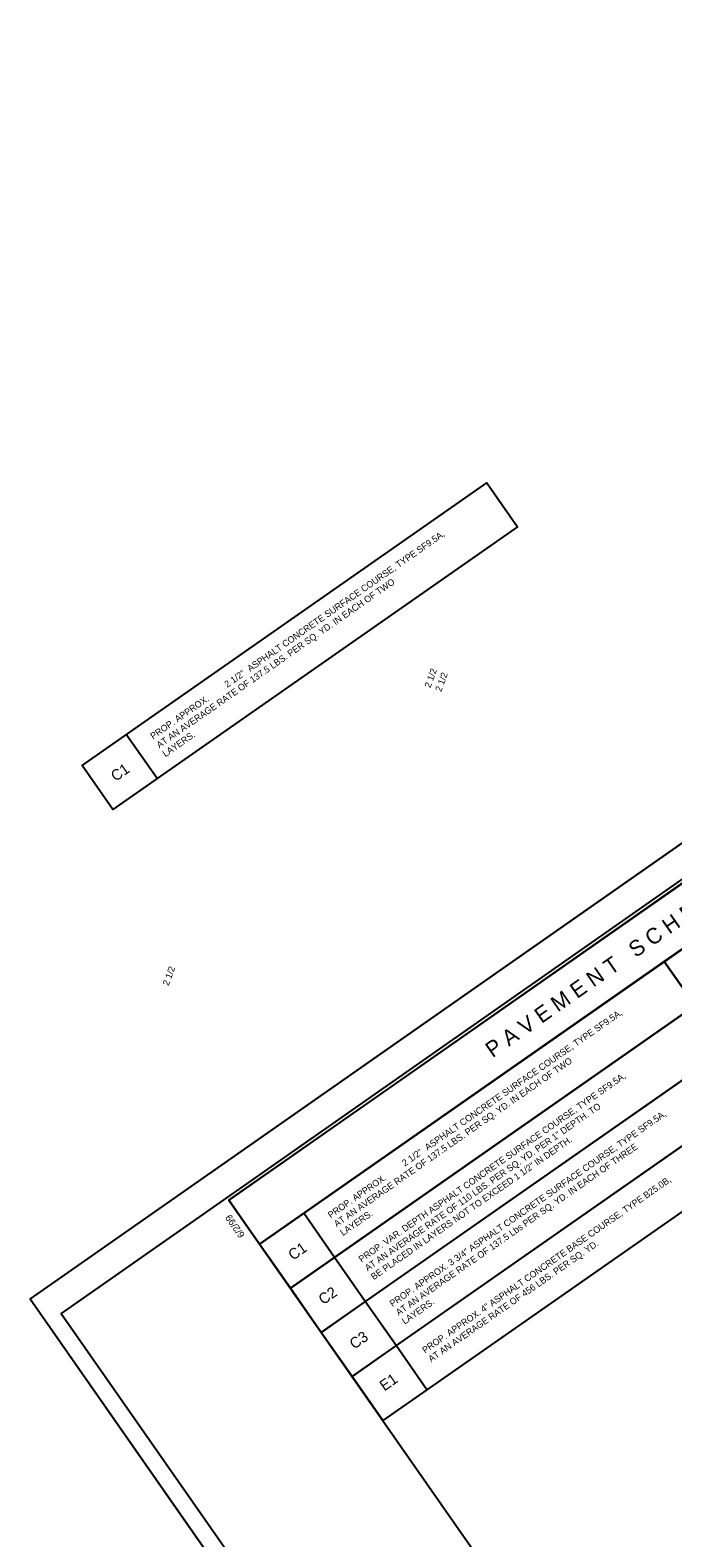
# Model space of a CAD drawing. Extents: x 1033697 to 1037131, y 657437 to 660507.
# Drawn here: x 1035031 to 1035520, y 659179 to 660325 of the extents above; entities that cross this region are included whole.
import ezdxf

# ---------------------------------------------------------------- set-up
doc = ezdxf.new("R2010")
doc.units = 0
for name, color, linetype in [('Default', 7, 'Continuous'), ('Prop Pavement Schedule Description CELL', 7, 'Continuous'), ('Sheet Cutting Line CELL', 7, 'Continuous'), ('Sheet Plot Border Inside CELL', 7, 'Continuous'), ('Sheet Plot Border Outside CELL', 7, 'Continuous'), ('Sheet Typical CELL', 7, 'Continuous')]:
    doc.layers.add(name, color=color, linetype=linetype)

msp = doc.modelspace()

# ---------------------------------------------------------------- linework, layer by layer
at = {"layer": 'Default'}
msp.add_lwpolyline([(1035286.1, 659358.4), (1035252.6, 659335), (1035229.1, 659368.5), (1035537, 659583.5), (1035560.5, 659549.9), (1035286.1, 659358.4), (1035262.7, 659391.9)], dxfattribs=at)
at = {"layer": 'Prop Pavement Schedule Description CELL'}
for p, q in [((1035276, 659301.4), (1035583.9, 659516.4)), ((1035607.3, 659482.9), (1035333, 659291.3)), ((1035333, 659291.3), (1035309.5, 659324.9)), ((1035299.4, 659267.9), (1035276, 659301.4)), ((1035333, 659291.3), (1035299.4, 659267.9))]:
    msp.add_line(p, q, dxfattribs=at)
for points in [[(1035127.6, 659756), (1035094.1, 659732.5), (1035070.6, 659766.1), (1035378.5, 659981), (1035401.9, 659947.5), (1035127.6, 659756), (1035104.1, 659789.5)], [(1035570.6, 659606.9), (1035537, 659583.5), (1035513.6, 659617), (1035828.9, 659836.6), (1035852.3, 659803.1), (1035570.6, 659606.9), (1035547.1, 659640.4)], [(1035262.7, 659391.9), (1035229.1, 659368.5), (1035205.7, 659402), (1035513.6, 659617), (1035537, 659583.5), (1035262.7, 659391.9), (1035239.2, 659425.5)], [(1035309.5, 659324.9), (1035276, 659301.4), (1035252.6, 659335), (1035560.5, 659549.9), (1035583.9, 659516.4), (1035309.5, 659324.9), (1035286.1, 659358.4)]]:
    msp.add_lwpolyline(points, dxfattribs=at)
msp.add_lwpolyline([(1035182.3, 659435.6), (1035805.5, 659870.1), (1035828.9, 659836.6), (1035205.7, 659402)], close=True, dxfattribs=at)
at = {"layer": 'Sheet Cutting Line CELL'}
for p, q in [((1036411.3, 660325.1), (1035031.1, 659360.4)), ((1035031.1, 659360.4), (1035661.2, 658458.8))]:
    msp.add_line(p, q, dxfattribs=at)
at = {"layer": 'Sheet Plot Border Inside CELL'}
msp.add_lwpolyline([(1036420.5, 660304.1), (1035054.6, 659349.4), (1035659, 658484.6), (1037024.9, 659439.3)], close=True, dxfattribs=at)
at = {"layer": 'Sheet Plot Border Outside CELL'}
msp.add_lwpolyline([(1036411.3, 660325.1), (1035031.1, 659360.4), (1035661.2, 658458.8), (1037041.5, 659423.5)], close=True, dxfattribs=at)
at = {"layer": 'Sheet Typical CELL'}
msp.add_lwpolyline([(1036411.7, 660294.9), (1035182.3, 659435.6), (1035783.8, 658574.9), (1037013.2, 659434.3)], close=True, dxfattribs=at)

# ---------------------------------------------------------------- texts
at = {"layer": 'Default'}
for s, height, rotation, p in [('2 1/2', 5, 69.9023, (1035335.6, 659824.7)), ('2 1/2', 5, 69.9023, (1035343.8, 659821.7)), ('2 1/2', 5, 69.9023, (1035136.4, 659598.2)), ('PROP. VAR. DEPTH ASPHALT CONCRETE SURFACE COURSE, TYPE SF9.5A,', 5, 34.9512, (1035283.2, 659388)), ('AT AN AVERAGE RATE OF 110 LBS. PER SQ. YD. PER 1" DEPTH. TO', 5, 34.9512, (1035287.9, 659381.3)), ('BE PLACED IN LAYERS NOT TO EXCEED 1 1/2" IN DEPTH.', 5, 34.9512, (1035292.5, 659374.6)), ('C2', 8.17, 34.9512, (1035254.1, 659355.6))]:
    msp.add_text(s, height=height, rotation=rotation, dxfattribs=at).set_placement(p)
at = {"layer": 'Prop Pavement Schedule Description CELL'}
for s, height, rotation, p in [(' ASPHALT CONCRETE SURFACE COURSE, TYPE SF9.5A, ', 5, 34.9512, (1035196.9, 659836)), ('AT AN AVERAGE RATE OF 137.5 LBS. PER SQ. YD. IN EACH OF TWO ', 5, 34.9512, (1035129.4, 659778.9)), ('2 1/2"', 5, 34.9512, (1035181.1, 659825)), ('PROP. APPROX. ', 5, 34.9512, (1035124.7, 659785.6)), ('LAYERS.', 5, 34.9512, (1035134, 659772.2)), ('C1', 8.17, 34.9512, (1035096.1, 659753.5)), ('P A V E M E N T   S C H E D U L E', 12, 34.9389, (1035382.9, 659543.4)), (' ASPHALT CONCRETE SURFACE COURSE, TYPE SF9.5A, ', 5, 34.9512, (1035332, 659472)), ('AT AN AVERAGE RATE OF 137.5 LBS. PER SQ. YD. IN EACH OF TWO ', 5, 34.9512, (1035264.4, 659414.8)), ('PROP. APPROX. 3 3/4" ASPHALT CONCRETE SURFACE COURSE, TYPE SF9.5A, ', 5, 34.9512, (1035306.8, 659354.2)), ('AT AN AVERAGE RATE OF 137.5 Lbs PER SQ. YD. IN EACH OF THREE ', 5, 34.9512, (1035311.5, 659347.5)), ('2 1/2"', 5, 34.9512, (1035316.2, 659461)), ('PROP. APPROX. ', 5, 34.9512, (1035259.8, 659421.5)), ('PROP. APPROX. 4" ASPHALT CONCRETE BASE COURSE, TYPE B25.0B,', 5, 34.9512, (1035331.6, 659318.8)), ('LAYERS.', 5, 34.9512, (1035269.1, 659408.1)), ('C1', 8.17, 34.9512, (1035231.1, 659389.4)), ('AT AN AVERAGE RATE OF 456 LBS. PER SQ. YD.', 5, 34.9512, (1035336.2, 659312.1)), ('LAYERS.', 5, 34.9512, (1035316.1, 659340.8)), ('C3', 8.17, 34.9512, (1035277.7, 659321.8)), ('E1', 8.17, 34.9512, (1035300.6, 659290))]:
    msp.add_text(s, height=height, rotation=rotation, dxfattribs=at).set_placement(p)
at = {"layer": 'Sheet Typical CELL'}
msp.add_text('6/2/99', height=5.25, rotation=124.9512, dxfattribs=at).set_placement((1035194.7, 659409.1))

doc.saveas('drawing.dxf')
